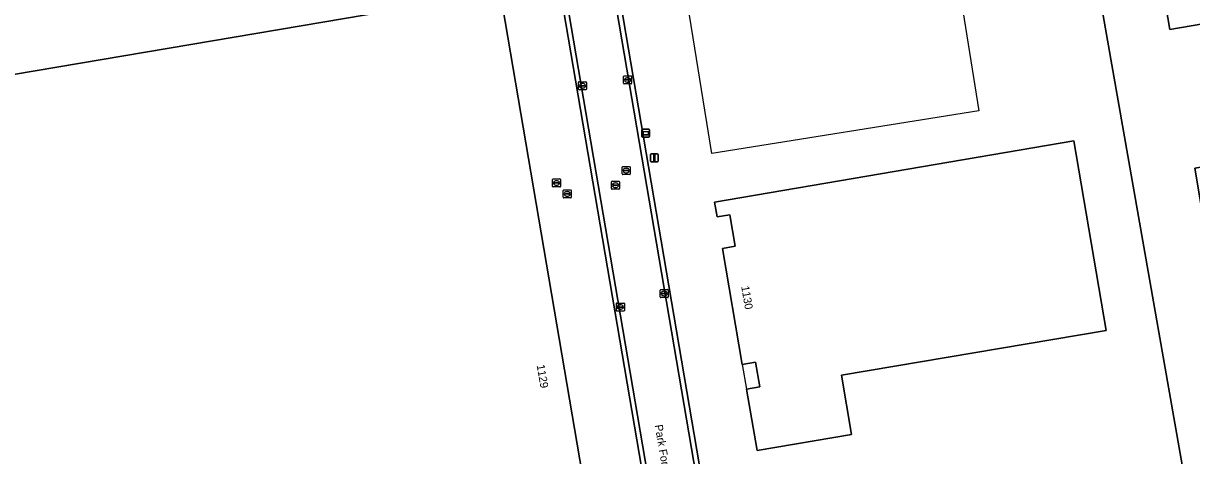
# Model space of a CAD drawing. Extents: x 154324 to 155744, y 382937 to 384188.
# Drawn here: x 154819.6 to 154965.6, y 383563.3 to 383617.3 of the extents above; entities that cross this region are included whole.
import ezdxf

# ---------------------------------------------------------------- set-up
doc = ezdxf.new("R2010")
doc.units = 0
for name, color, linetype in [('IMGEO_Erf', 7, 'Continuous'), ('IMGEO_Grasland_agrarisch', 7, 'Continuous'), ('IMGEO_Kolk', 7, 'Continuous'), ('IMGEO_Lichtmast', 7, 'Continuous'), ('IMGEO_Openbare_ruimte_label', 7, 'Continuous'), ('IMGEO_Pand', 7, 'Continuous'), ('IMGEO_Pand_nummerreeks', 7, 'Continuous'), ('IMGEO_Pand_overbouw', 7, 'Continuous'), ('IMGEO_Pand_vergunning_verleend', 7, 'Continuous'), ('IMGEO_Rijbaan_lokaal_gesloten', 7, 'Continuous'), ('IMGEO_Rijbaan_lokaal_open', 7, 'Continuous'), ('IMGEO_Rioolput', 7, 'Continuous'), ('IMGEO_Verklikker', 7, 'Continuous')]:
    doc.layers.add(name, color=color, linetype=linetype)

msp = doc.modelspace()

# ---------------------------------------------------------------- linework, layer by layer
at = {"layer": 'IMGEO_Erf'}
for points in [[(154715.12, 383606.17), (154717.25, 383593.65), (154799.26, 383607.57), (154796.3, 383624.97), (154807.03, 383626.73), (154809.97, 383609.47), (154879.18, 383621.22), (154872.98, 383657.63), (154872.88, 383657.62), (154870.05, 383657.16), (154869.54, 383660.13), (154872.55, 383660.65), (154872.56, 383660.61), (154875.75, 383661.08), (154876.27, 383658.02), (154880.3, 383658.76), (154878.39, 383669.9), (154870.94, 383668.6), (154867.57, 383688.39), (154787.88, 383674.89), (154786.54, 383674.89), (154790.1, 383654.95), (154709.26, 383640.72)], [(154968.86, 383582.04), (154965.97, 383599.17), (154982.68, 383602.01), (154981.86, 383606.81), (154988.34, 383607.92), (154989.34, 383602.11), (154999, 383603.75), (154995.75, 383622.1), (154986.05, 383620.46), (154986.86, 383615.62), (154980.37, 383614.53), (154979.57, 383619.36), (154962.83, 383616.51), (154959.94, 383633.57), (155019.3, 383643.68), (155023.47, 383619.23), (155022.4, 383619.04), (155023.51, 383612.46), (155024.59, 383612.65), (155025.35, 383608.21), (155028.11, 383592.03)]]:
    msp.add_lwpolyline(points, close=True, dxfattribs=at)
for points in [[(154880.33, 383658.59), (154880.3, 383658.76), (154876.27, 383658.02), (154875.75, 383661.08), (154872.56, 383660.61), (154873.07, 383657.65), (154872.98, 383657.63), (154879.18, 383621.22), (154895.55, 383525.1), (154815.63, 383511.49)], [(154957.64, 383205.01), (154955.13, 383219.62), (154933.06, 383349.39), (154931.45, 383358.87), (154880.33, 383658.59)], [(154949.33, 383647.91), (154982.71, 383457.88)]]:
    msp.add_lwpolyline(points, dxfattribs=at)
at = {"layer": 'IMGEO_Grasland_agrarisch'}
for points in [[(154886.01, 383668.1), (154936.69, 383370.6), (154936.7, 383370.54), (154939.6, 383371.04), (154941.3, 383371.33), (154964.54, 383375.32), (154995.11, 383380.56), (154999.88, 383352.45)], [(155069.43, 383341.54), (155066.21, 383389.86), (155065.71, 383396.48), (155059.76, 383395.85), (155012.63, 383387.85), (154994.32, 383384.62), (154989.66, 383412.19), (154987.44, 383425.44), (154984.95, 383439.95), (154985.61, 383440.02), (154982.63, 383457.87), (154982.71, 383457.88), (154949.33, 383647.91)]]:
    msp.add_lwpolyline(points, dxfattribs=at)
msp.add_lwpolyline([(154921.83, 383573.32), (154923.09, 383565.9), (154911.27, 383563.9), (154909.96, 383571.56), (154911.63, 383571.85), (154911.1, 383574.94), (154909.43, 383574.65), (154906.95, 383589.16), (154908.56, 383589.42), (154907.89, 383593.37), (154906.28, 383593.1), (154905.97, 383594.94), (154950.87, 383602.6), (154954.89, 383578.91)], close=True, dxfattribs=at)
at = {"layer": 'IMGEO_Kolk'}
for p, q in [((154894.61, 383609.78), (154894.61, 383610.63)), ((154894.68, 383610.71), (154895.53, 383610.71)), ((154894.86, 383610.2), (154894.86, 383610.21)), ((154895.3, 383610.16), (154894.9, 383610.16)), ((154894.91, 383610.25), (154895.31, 383610.25)), ((154895.09, 383610.48), (154895.12, 383610.48)), ((154895.35, 383610.21), (154895.35, 383610.2)), ((154895.61, 383610.63), (154895.61, 383609.78)), ((154888.97, 383609.05), (154888.97, 383609.9)), ((154889.04, 383609.97), (154889.89, 383609.97)), ((154889.89, 383608.97), (154889.04, 383608.97)), ((154889.23, 383609.47), (154889.23, 383609.48)), ((154889.27, 383609.52), (154889.67, 383609.52)), ((154889.66, 383609.43), (154889.27, 383609.43)), ((154889.48, 383609.19), (154889.45, 383609.19)), ((154889.46, 383609.75), (154889.48, 383609.75)), ((154889.71, 383609.48), (154889.71, 383609.47)), ((154889.97, 383609.9), (154889.97, 383609.05)), ((154895.53, 383609.7), (154894.68, 383609.7)), ((154895.12, 383609.93), (154895.09, 383609.93)), ((154899.17, 383583.09), (154899.17, 383583.94)), ((154899.25, 383584.02), (154900.1, 383584.02)), ((154899.66, 383583.8), (154899.69, 383583.8)), ((154900.17, 383583.94), (154900.17, 383583.09)), ((154900.1, 383583.02), (154899.25, 383583.02)), ((154899.43, 383583.51), (154899.43, 383583.52)), ((154899.47, 383583.56), (154899.87, 383583.56)), ((154899.87, 383583.47), (154899.47, 383583.47)), ((154899.68, 383583.24), (154899.66, 383583.24)), ((154899.92, 383583.52), (154899.92, 383583.51)), ((154893.7, 383581.4), (154893.7, 383582.26)), ((154893.77, 383582.33), (154894.62, 383582.33)), ((154894.62, 383581.33), (154893.77, 383581.33)), ((154893.95, 383581.82), (154893.95, 383581.84)), ((154894.39, 383581.79), (154893.99, 383581.79)), ((154894, 383581.87), (154894.39, 383581.87)), ((154894.18, 383582.11), (154894.21, 383582.11)), ((154894.21, 383581.55), (154894.18, 383581.55)), ((154894.44, 383581.84), (154894.44, 383581.82)), ((154894.7, 383582.26), (154894.7, 383581.4))]:
    msp.add_line(p, q, dxfattribs=at)
for points in [[(154894.61, 383609.78), (154894.61, 383610.63)], [(154894.68, 383610.71), (154895.53, 383610.71)], [(154895.61, 383610.63), (154895.61, 383609.78)], [(154888.97, 383609.05), (154888.97, 383609.9)], [(154889.04, 383609.97), (154889.89, 383609.97)], [(154889.89, 383608.97), (154889.04, 383608.97)], [(154889.97, 383609.9), (154889.97, 383609.05)], [(154895.53, 383609.7), (154894.68, 383609.7)], [(154899.17, 383583.09), (154899.17, 383583.94)], [(154899.25, 383584.02), (154900.1, 383584.02)], [(154900.17, 383583.94), (154900.17, 383583.09)], [(154900.1, 383583.02), (154899.25, 383583.02)], [(154893.7, 383581.4), (154893.7, 383582.26)], [(154893.77, 383582.33), (154894.62, 383582.33)], [(154894.62, 383581.33), (154893.77, 383581.33)], [(154894.7, 383582.26), (154894.7, 383581.4)]]:
    msp.add_lwpolyline(points, dxfattribs=at)
for centre, radius, start, end in [((154894.68, 383610.63), 0.0765, 91.552, 178.448), ((154894.68, 383610.63), 0.0765, 91.552, 178.448), ((154894.91, 383610.21), 0.0403, 85.8775, 175.7526), ((154894.9, 383610.2), 0.0366, 178.938, 274.7102), ((154895.31, 383610.2), 0.043, 264.8664, 352.4533), ((154895.31, 383610.21), 0.0386, 1.7309, 96.639), ((154895.53, 383610.63), 0.0765, 1.552, 88.448), ((154895.53, 383610.63), 0.0765, 1.552, 88.448), ((154889.04, 383609.9), 0.0765, 91.552, 178.448), ((154889.04, 383609.9), 0.0765, 91.552, 178.448), ((154889.04, 383609.05), 0.0765, 181.552, 268.448), ((154889.04, 383609.05), 0.0765, 181.552, 268.448), ((154889.27, 383609.48), 0.0403, 85.8775, 175.7526), ((154889.26, 383609.47), 0.0366, 178.938, 274.7102), ((154889.67, 383609.47), 0.043, 264.8664, 352.4533), ((154889.67, 383609.48), 0.0386, 1.7309, 96.639), ((154889.89, 383609.9), 0.0765, 1.552, 88.448), ((154889.89, 383609.9), 0.0765, 1.552, 88.448), ((154889.89, 383609.05), 0.0765, 271.552, 358.448), ((154889.89, 383609.05), 0.0765, 271.552, 358.448), ((154894.68, 383609.78), 0.0765, 181.552, 268.448), ((154894.68, 383609.78), 0.0765, 181.552, 268.448), ((154895.53, 383609.78), 0.0765, 271.552, 358.448), ((154895.53, 383609.78), 0.0765, 271.552, 358.448), ((154899.25, 383583.94), 0.0765, 91.552, 178.448), ((154899.25, 383583.94), 0.0765, 91.552, 178.448), ((154900.1, 383583.94), 0.0765, 1.552, 88.448), ((154900.1, 383583.94), 0.0765, 1.552, 88.448), ((154899.25, 383583.09), 0.0765, 181.552, 268.448), ((154899.25, 383583.09), 0.0765, 181.552, 268.448), ((154899.47, 383583.52), 0.0403, 85.8775, 175.7526), ((154899.47, 383583.51), 0.0366, 178.938, 274.7102), ((154899.88, 383583.52), 0.0386, 1.7309, 96.639), ((154899.87, 383583.52), 0.043, 264.8664, 352.4533), ((154900.1, 383583.09), 0.0765, 271.552, 358.448), ((154900.1, 383583.09), 0.0765, 271.552, 358.448), ((154893.77, 383582.25), 0.0765, 91.552, 178.448), ((154893.77, 383582.25), 0.0765, 91.552, 178.448), ((154893.77, 383581.4), 0.0765, 181.552, 268.448), ((154893.77, 383581.4), 0.0765, 181.552, 268.448), ((154893.99, 383581.83), 0.0403, 85.8775, 175.7526), ((154893.99, 383581.82), 0.0366, 178.938, 274.7102), ((154894.4, 383581.83), 0.0386, 1.7309, 96.639), ((154894.4, 383581.83), 0.043, 264.8664, 352.4533), ((154894.62, 383582.25), 0.0765, 1.552, 88.448), ((154894.62, 383582.25), 0.0765, 1.552, 88.448), ((154894.62, 383581.4), 0.0765, 271.552, 358.448), ((154894.62, 383581.4), 0.0765, 271.552, 358.448)]:
    msp.add_arc(centre, radius, start, end, dxfattribs=at)
for centre, major_axis, ratio, start_param, end_param in [((154895.09, 383610.2), (-0.387, 0.002), 0.722429, 4.712389, 7.853982), ((154895.12, 383610.2), (-0.39, 0.002), 0.717154, 1.570796, 4.712389), ((154889.45, 383609.47), (-0.387, 0.002), 0.722429, 4.712389, 7.853982), ((154889.48, 383609.47), (-0.39, 0.002), 0.717154, 1.570796, 4.712389), ((154899.66, 383583.52), (-0.387, 0.002), 0.722429, 4.712389, 7.853982), ((154899.68, 383583.52), (-0.39, 0.002), 0.717154, 1.570796, 4.712389), ((154894.18, 383581.83), (-0.387, 0.002), 0.722429, 4.712389, 7.853982), ((154894.21, 383581.83), (-0.39, 0.002), 0.717154, 1.570796, 4.712389)]:
    msp.add_ellipse(centre, major_axis=major_axis, ratio=ratio, start_param=start_param, end_param=end_param, dxfattribs=at)
at = {"layer": 'IMGEO_Lichtmast'}
for p, q in [((154897.95, 383600.07), (154897.95, 383600.87)), ((154897.95, 383600.87), (154897.95, 383600.07)), ((154898.05, 383600.97), (154898.84, 383600.97)), ((154898.84, 383600.97), (154898.05, 383600.97)), ((154898.84, 383599.97), (154898.05, 383599.97)), ((154898.05, 383599.97), (154898.84, 383599.97)), ((154898.94, 383600.87), (154898.94, 383600.07)), ((154898.94, 383600.07), (154898.94, 383600.87))]:
    msp.add_line(p, q, dxfattribs=at)
msp.add_lwpolyline([(154898.37, 383600.85), (154898.52, 383600.85), (154898.52, 383600.1), (154898.37, 383600.1), (154898.37, 383600.85)], dxfattribs=at)
for centre, start, end in [((154898.05, 383600.87), 90, 180), ((154898.05, 383600.87), 90, 180), ((154898.05, 383600.07), 180, 270), ((154898.05, 383600.07), 180, 270), ((154898.84, 383600.87), 0, 90), ((154898.84, 383600.87), 360, 90), ((154898.84, 383600.07), 270, 0), ((154898.84, 383600.07), 270, 0)]:
    msp.add_arc(centre, 0.1, start, end, dxfattribs=at)
at = {"layer": 'IMGEO_Pand'}
for points in [[(155022.4, 383619.04), (155023.47, 383619.23), (155019.3, 383643.68), (154959.94, 383633.57), (154962.83, 383616.51), (154979.57, 383619.36), (154980.37, 383614.53), (154986.86, 383615.62), (154986.05, 383620.46), (154995.75, 383622.1), (154999, 383603.75), (154989.34, 383602.11), (154988.34, 383607.92), (154981.86, 383606.81), (154982.68, 383602.01), (154965.97, 383599.17), (154968.86, 383582.04), (155028.11, 383592.03), (155025.35, 383608.21), (155024.59, 383612.65), (155023.51, 383612.46)], [(154879.18, 383621.22), (154809.97, 383609.47), (154807.03, 383626.73), (154796.3, 383624.97), (154799.26, 383607.57), (154717.25, 383593.65), (154717.21, 383593.64), (154733.53, 383497.52), (154738.94, 383498.45), (154769.14, 383503.59), (154815.63, 383511.49), (154895.55, 383525.1)], [(154950.87, 383602.6), (154905.97, 383594.94), (154906.28, 383593.1), (154907.89, 383593.37), (154908.56, 383589.42), (154906.95, 383589.16), (154909.43, 383574.65), (154911.1, 383574.94), (154911.63, 383571.85), (154909.96, 383571.56), (154911.27, 383563.9), (154923.09, 383565.9), (154921.83, 383573.32), (154954.89, 383578.91)]]:
    msp.add_lwpolyline(points, close=True, dxfattribs=at)
at = {"layer": 'IMGEO_Pand_overbouw'}
msp.add_lwpolyline([(154909.96, 383571.56), (154911.63, 383571.85), (154911.1, 383574.94), (154909.43, 383574.65)], close=True, dxfattribs=at)
at = {"layer": 'IMGEO_Pand_vergunning_verleend'}
msp.add_lwpolyline([(154900.72, 383631.49), (154934.09, 383636.84), (154938.99, 383606.36), (154905.61, 383601.01)], close=True, dxfattribs=at)
at = {"layer": 'IMGEO_Rijbaan_lokaal_gesloten'}
for points in [[(154854.43, 383814.31), (154854.65, 383812.99), (154854.81, 383812.02), (154858.48, 383790.5), (154869.56, 383725.26), (154869.6, 383725.13), (154932.04, 383358.96), (154933.66, 383349.45), (154956.05, 383217.96), (154957.68, 383208.02), (154958.22, 383204.74)], [(154961.84, 383219.4), (154937.89, 383359.92), (154875.73, 383724.69)]]:
    msp.add_lwpolyline(points, dxfattribs=at)
at = {"layer": 'IMGEO_Rijbaan_lokaal_open'}
for points in [[(154859.21, 383821.78), (154860.59, 383813.67), (154872.99, 383740.87), (154875.26, 383727.61), (154875.73, 383724.69), (154937.89, 383359.92), (154938.49, 383360.02), (154937.7, 383364.67), (154936.71, 383370.48), (154936.7, 383370.54), (154936.69, 383370.6), (154886.01, 383668.1)], [(154853.94, 383813.59), (154856.18, 383800.4), (154857.87, 383790.41), (154868.95, 383725.16), (154878.39, 383669.9), (154880.3, 383658.76), (154880.33, 383658.59), (154931.45, 383358.87), (154932.04, 383358.96), (154869.6, 383725.13), (154869.56, 383725.26), (154858.48, 383790.5), (154854.81, 383812.02), (154854.65, 383812.99), (154854.43, 383814.31)]]:
    msp.add_lwpolyline(points, dxfattribs=at)
at = {"layer": 'IMGEO_Rioolput'}
for p, q in [((154894.43, 383598.46), (154894.43, 383599.31)), ((154894.51, 383599.38), (154895.36, 383599.38)), ((154894.69, 383598.88), (154894.69, 383598.89)), ((154895.13, 383598.84), (154894.73, 383598.84)), ((154894.74, 383598.93), (154895.13, 383598.93)), ((154894.92, 383599.16), (154894.95, 383599.16)), ((154894.94, 383598.6), (154894.92, 383598.6)), ((154895.18, 383598.89), (154895.18, 383598.88)), ((154895.43, 383599.31), (154895.43, 383598.46)), ((154885.72, 383596.9), (154885.72, 383597.76)), ((154885.8, 383597.83), (154886.65, 383597.83)), ((154885.98, 383597.32), (154885.98, 383597.34)), ((154886.02, 383597.37), (154886.42, 383597.37)), ((154886.42, 383597.29), (154886.02, 383597.29)), ((154886.21, 383597.61), (154886.24, 383597.61)), ((154886.23, 383597.05), (154886.21, 383597.05)), ((154886.47, 383597.34), (154886.47, 383597.32)), ((154886.72, 383597.76), (154886.72, 383596.9)), ((154893.09, 383596.63), (154893.09, 383597.48)), ((154893.16, 383597.55), (154894.01, 383597.55)), ((154893.34, 383597.05), (154893.34, 383597.06)), ((154893.78, 383597.01), (154893.38, 383597.01)), ((154893.39, 383597.1), (154893.78, 383597.1)), ((154893.57, 383597.33), (154893.6, 383597.33)), ((154893.83, 383597.06), (154893.83, 383597.05)), ((154894.09, 383597.48), (154894.09, 383596.63)), ((154895.36, 383598.38), (154894.51, 383598.38)), ((154886.65, 383596.83), (154885.8, 383596.83)), ((154887.06, 383595.54), (154887.06, 383596.4)), ((154887.14, 383596.47), (154887.99, 383596.47)), ((154887.32, 383595.96), (154887.32, 383595.98)), ((154887.76, 383595.93), (154887.36, 383595.93)), ((154887.37, 383596.01), (154887.76, 383596.01)), ((154887.55, 383596.25), (154887.58, 383596.25)), ((154887.57, 383595.69), (154887.55, 383595.69)), ((154887.81, 383595.98), (154887.81, 383595.96)), ((154888.07, 383596.4), (154888.07, 383595.54)), ((154894.01, 383596.55), (154893.16, 383596.55)), ((154893.6, 383596.77), (154893.57, 383596.77)), ((154887.99, 383595.47), (154887.14, 383595.47))]:
    msp.add_line(p, q, dxfattribs=at)
for points in [[(154894.43, 383598.46), (154894.43, 383599.31)], [(154894.51, 383599.38), (154895.36, 383599.38)], [(154895.43, 383599.31), (154895.43, 383598.46)], [(154885.72, 383596.9), (154885.72, 383597.76)], [(154885.8, 383597.83), (154886.65, 383597.83)], [(154886.72, 383597.76), (154886.72, 383596.9)], [(154893.09, 383596.63), (154893.09, 383597.48)], [(154893.16, 383597.55), (154894.01, 383597.55)], [(154894.09, 383597.48), (154894.09, 383596.63)], [(154895.36, 383598.38), (154894.51, 383598.38)], [(154886.65, 383596.83), (154885.8, 383596.83)], [(154887.06, 383595.54), (154887.06, 383596.4)], [(154887.14, 383596.47), (154887.99, 383596.47)], [(154888.07, 383596.4), (154888.07, 383595.54)], [(154894.01, 383596.55), (154893.16, 383596.55)], [(154887.99, 383595.47), (154887.14, 383595.47)]]:
    msp.add_lwpolyline(points, dxfattribs=at)
for centre, radius, start, end in [((154894.51, 383599.31), 0.0765, 91.552, 178.448), ((154894.51, 383599.31), 0.0765, 91.552, 178.448), ((154894.51, 383598.46), 0.0765, 181.552, 268.448), ((154894.51, 383598.46), 0.0765, 181.552, 268.448), ((154894.73, 383598.89), 0.0403, 85.8775, 175.7526), ((154894.73, 383598.88), 0.0366, 178.938, 274.7102), ((154895.14, 383598.89), 0.0386, 1.7309, 96.639), ((154895.13, 383598.88), 0.043, 264.8664, 352.4533), ((154895.36, 383599.31), 0.0765, 1.552, 88.448), ((154895.36, 383599.31), 0.0765, 1.552, 88.448), ((154895.36, 383598.46), 0.0765, 271.552, 358.448), ((154895.36, 383598.46), 0.0765, 271.552, 358.448), ((154885.8, 383597.75), 0.0765, 91.552, 178.448), ((154885.8, 383597.75), 0.0765, 91.552, 178.448), ((154886.02, 383597.33), 0.0403, 85.8775, 175.7526), ((154886.02, 383597.32), 0.0366, 178.938, 274.7102), ((154886.43, 383597.33), 0.0386, 1.7309, 96.639), ((154886.42, 383597.33), 0.043, 264.8664, 352.4533), ((154886.65, 383597.75), 0.0765, 1.552, 88.448), ((154886.65, 383597.75), 0.0765, 1.552, 88.448), ((154893.16, 383597.48), 0.0765, 91.552, 178.448), ((154893.16, 383597.48), 0.0765, 91.552, 178.448), ((154893.38, 383597.06), 0.0403, 85.8775, 175.7526), ((154893.38, 383597.05), 0.0366, 178.938, 274.7102), ((154893.79, 383597.06), 0.0386, 1.7309, 96.639), ((154893.79, 383597.05), 0.043, 264.8664, 352.4533), ((154894.01, 383597.48), 0.0765, 1.552, 88.448), ((154894.01, 383597.48), 0.0765, 1.552, 88.448), ((154885.8, 383596.91), 0.0765, 181.552, 268.448), ((154885.8, 383596.91), 0.0765, 181.552, 268.448), ((154886.65, 383596.91), 0.0765, 271.552, 358.448), ((154886.65, 383596.91), 0.0765, 271.552, 358.448), ((154887.14, 383596.39), 0.0765, 91.552, 178.448), ((154887.14, 383596.39), 0.0765, 91.552, 178.448), ((154887.14, 383595.54), 0.0765, 181.552, 268.448), ((154887.14, 383595.54), 0.0765, 181.552, 268.448), ((154887.36, 383595.97), 0.0403, 85.8775, 175.7526), ((154887.36, 383595.96), 0.0366, 178.938, 274.7102), ((154887.77, 383595.97), 0.0386, 1.7309, 96.639), ((154887.76, 383595.97), 0.043, 264.8664, 352.4533), ((154887.99, 383596.39), 0.0765, 1.552, 88.448), ((154887.99, 383596.39), 0.0765, 1.552, 88.448), ((154887.99, 383595.54), 0.0765, 271.552, 358.448), ((154887.99, 383595.54), 0.0765, 271.552, 358.448), ((154893.16, 383596.63), 0.0765, 181.552, 268.448), ((154893.16, 383596.63), 0.0765, 181.552, 268.448), ((154894.01, 383596.63), 0.0765, 271.552, 358.448), ((154894.01, 383596.63), 0.0765, 271.552, 358.448)]:
    msp.add_arc(centre, radius, start, end, dxfattribs=at)
for centre, major_axis, ratio, start_param, end_param in [((154894.92, 383598.88), (-0.387, 0.002), 0.722429, 4.712389, 7.853982), ((154894.94, 383598.88), (-0.39, 0.002), 0.717154, 1.570796, 4.712389), ((154886.21, 383597.33), (-0.387, 0.002), 0.722429, 4.712389, 7.853982), ((154886.23, 383597.33), (-0.39, 0.002), 0.717154, 1.570796, 4.712389), ((154893.57, 383597.05), (-0.387, 0.002), 0.722429, 4.712389, 7.853982), ((154893.6, 383597.05), (-0.39, 0.002), 0.717154, 1.570796, 4.712389), ((154887.55, 383595.97), (-0.387, 0.002), 0.722429, 4.712389, 7.853982), ((154887.58, 383595.97), (-0.39, 0.002), 0.717154, 1.570796, 4.712389)]:
    msp.add_ellipse(centre, major_axis=major_axis, ratio=ratio, start_param=start_param, end_param=end_param, dxfattribs=at)
at = {"layer": 'IMGEO_Verklikker'}
for p, q in [((154896.87, 383603.15), (154896.87, 383603.95)), ((154896.87, 383603.95), (154896.87, 383603.15)), ((154896.97, 383604.05), (154897.76, 383604.05)), ((154897.76, 383604.05), (154896.97, 383604.05)), ((154897.76, 383603.05), (154896.97, 383603.05)), ((154896.97, 383603.05), (154897.76, 383603.05)), ((154897.86, 383603.95), (154897.86, 383603.15)), ((154897.86, 383603.15), (154897.86, 383603.95))]:
    msp.add_line(p, q, dxfattribs=at)
for points in [[(154896.98, 383603.78), (154897.76, 383603.78), (154897.76, 383603.32), (154896.98, 383603.32), (154896.98, 383603.78)], [(154897.04, 383603.72), (154897.04, 383603.38), (154897.7, 383603.38), (154897.7, 383603.72), (154897.04, 383603.72)]]:
    msp.add_lwpolyline(points, dxfattribs=at)
for centre, start, end in [((154896.97, 383603.95), 90, 180), ((154896.97, 383603.95), 90, 180), ((154896.97, 383603.15), 180, 270), ((154896.97, 383603.15), 180, 270), ((154897.76, 383603.95), 0, 90), ((154897.76, 383603.95), 360, 90), ((154897.76, 383603.15), 270, 0), ((154897.76, 383603.15), 270, 0)]:
    msp.add_arc(centre, 0.1, start, end, dxfattribs=at)

# ---------------------------------------------------------------- texts
at = {"layer": 'IMGEO_Openbare_ruimte_label'}
msp.add_text('Park Forum', height=1, rotation=279.6695, dxfattribs=at).set_placement((154898.48, 383567.06))
at = {"layer": 'IMGEO_Pand_nummerreeks'}
for s, rotation, p in [('1130', 279.7, (154909.29, 383584.4)), ('1129', 279.7573, (154883.74, 383574.56))]:
    msp.add_text(s, height=1, rotation=rotation, dxfattribs=at).set_placement(p)

doc.saveas('drawing.dxf')
